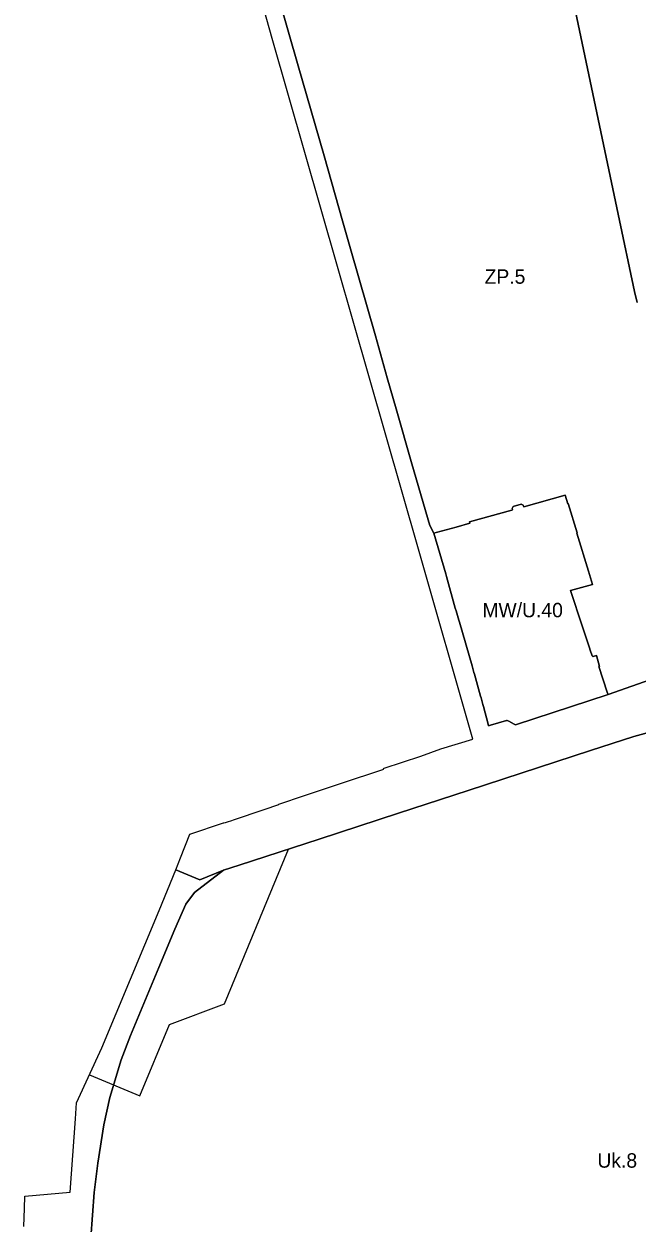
# Model space of a CAD drawing. Extents: x 7423367 to 7424726, y 5546744 to 5548391.
# Drawn here: x 7423569.6 to 7423781.7, y 5546954.8 to 5547370 of the extents above; entities that cross this region are included whole.
import ezdxf

# ---------------------------------------------------------------- set-up
doc = ezdxf.new("R2010")
doc.units = 0
for name, color, linetype in [('linie_rozgraniczajace', 7, 'Continuous'), ('linie_zabudowy_nieprzekraczalne', 7, 'Continuous'), ('oznaczenia_przeznaczen', 7, 'Continuous')]:
    doc.layers.add(name, color=color, linetype=linetype)

msp = doc.modelspace()

# ---------------------------------------------------------------- linework, layer by layer
at = {"layer": 'linie_rozgraniczajace'}
for points in [[(7423787.83, 5547125.26), (7423780.68, 5547123.28), (7423765.65, 5547118.41), (7423735.68, 5547108.59), (7423729.02, 5547106.4), (7423718.38, 5547102.92), (7423699.17, 5547096.68), (7423671.73, 5547087.7), (7423644.07, 5547078.72), (7423638.64, 5547076.94), (7423630.48, 5547073.59), (7423622.16, 5547077.15), (7423623.74, 5547081.23), (7423626.97, 5547089.49), (7423638.59, 5547093.34), (7423638.78, 5547093.4), (7423638.81, 5547093.32), (7423639.39, 5547093.51), (7423639.97, 5547093.7), (7423641.57, 5547094.23), (7423642.16, 5547094.43), (7423652.72, 5547097.96), (7423657.82, 5547099.67), (7423657.77, 5547099.82), (7423666.7, 5547102.83), (7423679.08, 5547106.95), (7423694.16, 5547111.96), (7423694.07, 5547112.18), (7423694.28, 5547112.25), (7423706.91, 5547116.4), (7423713.8, 5547118.96), (7423724.93, 5547122.34), (7423706.18, 5547188.14), (7423655.54, 5547364.92), (7423618.57, 5547496.4)], [(7423781.77, 5547273.48), (7423780.9, 5547277.38), (7423775.28, 5547304.1), (7423757.71, 5547387.52)], [(7423757.71, 5547387.52), (7423775.28, 5547304.1), (7423780.9, 5547277.38), (7423781.77, 5547273.48)], [(7423788.2, 5547143.63), (7423771.74, 5547137.77), (7423771.72, 5547137.85), (7423771.46, 5547138.61), (7423768.5, 5547147.45), (7423768.81, 5547147.55), (7423767.77, 5547151.28), (7423766.58, 5547150.97), (7423766.4, 5547150.92), (7423766.27, 5547151.25), (7423765.58, 5547153.15), (7423765.31, 5547153.97), (7423762.75, 5547161.61), (7423758.68, 5547173.8), (7423766.38, 5547175.94), (7423764.9, 5547180.46), (7423760.92, 5547193.71), (7423761.04, 5547193.74), (7423757.96, 5547203.93), (7423757.79, 5547203.88), (7423756.89, 5547206.82), (7423742.54, 5547202.79), (7423742.39, 5547203.31), (7423741.69, 5547203.69), (7423738.88, 5547202.93), (7423738.53, 5547202.2), (7423738.68, 5547201.76), (7423738.39, 5547201.68), (7423723.74, 5547197.63), (7423723.89, 5547197.11), (7423719.16, 5547195.76), (7423712.24, 5547193.88), (7423711.49, 5547193.68), (7423710.06, 5547196.29), (7423703.87, 5547217.66), (7423698.43, 5547236.75), (7423695.33, 5547247.46), (7423691.22, 5547262.02), (7423682.62, 5547292.16), (7423679.87, 5547301.84), (7423673.43, 5547324.29), (7423664.51, 5547355.5), (7423657.58, 5547379.7)], [(7423657.58, 5547379.7), (7423664.51, 5547355.5), (7423673.43, 5547324.29), (7423679.87, 5547301.84), (7423682.62, 5547292.16), (7423691.22, 5547262.02), (7423695.33, 5547247.46), (7423698.43, 5547236.75), (7423703.87, 5547217.66), (7423710.06, 5547196.29), (7423711.49, 5547193.68), (7423715.57, 5547179.63), (7423715.85, 5547178.7), (7423718.86, 5547167.69), (7423719.16, 5547166.78), (7423720.06, 5547163.59), (7423720.26, 5547162.85), (7423724.65, 5547147.79), (7423725.3, 5547145.48), (7423725.47, 5547144.86), (7423727.59, 5547137.26), (7423727.78, 5547136.65), (7423728.4, 5547134.29), (7423728.58, 5547133.68), (7423730.22, 5547127.58), (7423730.36, 5547126.99), (7423731, 5547127.18), (7423736.6, 5547128.78), (7423736.83, 5547128.85), (7423737.37, 5547128.56), (7423739.28, 5547127.53), (7423739.71, 5547127.29), (7423771.72, 5547137.85), (7423771.74, 5547137.77), (7423788.2, 5547143.63)], [(7423592.77, 5546949.66), (7423593.93, 5546965.34), (7423595.18, 5546975.55), (7423597.19, 5546988.79), (7423599.31, 5546998.31), (7423603.23, 5547011.33), (7423606.51, 5547019.77), (7423616.23, 5547043.23), (7423621.81, 5547056.59), (7423625.65, 5547065.18), (7423628.56, 5547069.28), (7423638.64, 5547076.94), (7423644.07, 5547078.72), (7423671.73, 5547087.7), (7423699.17, 5547096.68), (7423718.38, 5547102.92), (7423729.02, 5547106.4), (7423735.68, 5547108.59), (7423765.65, 5547118.41), (7423780.68, 5547123.28), (7423787.83, 5547125.26)], [(7423569.6, 5546953.61), (7423569.77, 5546959.82), (7423569.9, 5546964.11), (7423585.58, 5546965.52), (7423587.48, 5546990.9), (7423587.75, 5546996.46), (7423596.56, 5547015.51), (7423616.37, 5547062.99), (7423622.16, 5547077.15), (7423630.48, 5547073.59), (7423638.64, 5547076.94), (7423628.56, 5547069.28), (7423625.65, 5547065.18), (7423621.81, 5547056.59), (7423616.23, 5547043.23), (7423606.51, 5547019.77), (7423603.23, 5547011.33), (7423599.31, 5546998.31), (7423597.19, 5546988.79), (7423595.18, 5546975.55), (7423593.93, 5546965.34), (7423592.77, 5546949.66)]]:
    msp.add_lwpolyline(points, dxfattribs=at)
msp.add_lwpolyline([(7423711.49, 5547193.68), (7423712.24, 5547193.88), (7423719.16, 5547195.76), (7423723.89, 5547197.11), (7423723.74, 5547197.63), (7423738.39, 5547201.68), (7423738.68, 5547201.76), (7423738.53, 5547202.2), (7423738.88, 5547202.93), (7423741.69, 5547203.69), (7423742.39, 5547203.31), (7423742.54, 5547202.79), (7423756.89, 5547206.82), (7423757.79, 5547203.88), (7423757.96, 5547203.93), (7423761.04, 5547193.74), (7423760.92, 5547193.71), (7423764.9, 5547180.46), (7423766.38, 5547175.94), (7423758.68, 5547173.8), (7423762.75, 5547161.61), (7423765.31, 5547153.97), (7423765.58, 5547153.15), (7423766.27, 5547151.25), (7423766.4, 5547150.92), (7423766.58, 5547150.97), (7423767.77, 5547151.28), (7423768.81, 5547147.55), (7423768.5, 5547147.45), (7423771.46, 5547138.61), (7423771.72, 5547137.85), (7423739.71, 5547127.29), (7423739.28, 5547127.53), (7423737.37, 5547128.56), (7423736.83, 5547128.85), (7423736.6, 5547128.78), (7423731, 5547127.18), (7423730.36, 5547126.99), (7423730.22, 5547127.58), (7423728.58, 5547133.68), (7423728.4, 5547134.29), (7423727.78, 5547136.65), (7423727.59, 5547137.26), (7423725.47, 5547144.86), (7423725.3, 5547145.48), (7423724.65, 5547147.79), (7423720.26, 5547162.85), (7423720.06, 5547163.59), (7423719.16, 5547166.78), (7423718.86, 5547167.69), (7423715.85, 5547178.7), (7423715.57, 5547179.63)], close=True, dxfattribs=at)
at = {"layer": 'linie_zabudowy_nieprzekraczalne'}
msp.add_lwpolyline([(7423592.29, 5547006.06), (7423609.73, 5546998.84), (7423619.93, 5547023.51), (7423638.99, 5547030.65), (7423661.19, 5547084.27)], dxfattribs=at)

# ---------------------------------------------------------------- texts
at = {"layer": 'oznaczenia_przeznaczen'}
for s, p in [('ZP.5', (7423728.99, 5547280.02)), ('MW/U.40', (7423728.23, 5547164.54)), ('Uk.8', (7423768.04, 5546973.96))]:
    msp.add_text(s, height=5, dxfattribs=at).set_placement(p)

doc.saveas('drawing.dxf')
